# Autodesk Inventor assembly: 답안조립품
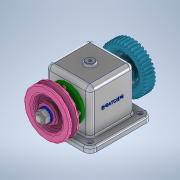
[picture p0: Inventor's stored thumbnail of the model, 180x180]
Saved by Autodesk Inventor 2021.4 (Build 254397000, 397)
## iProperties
Created: 2022-07
Part Number: 답안조립품
Document SubType Name: Assembly
Designer: j
Author: j
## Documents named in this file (12)
- C:\Users\j\Desktop\720706V1003\답안조립품.iam
- C:\Users\j\Desktop\720706V1003\본체.ipt
- C:\Users\j\Desktop\720706V1003\V벨트풀리.ipt
- C:\Users\j\Desktop\720706V1003\너트 M12x1.25.ipt
- C:\Users\j\Desktop\720706V1003\베어링 6204.ipt
- C:\Users\j\Desktop\720706V1003\볼트 M4x0.7.ipt
- C:\Users\j\Desktop\720706V1003\스퍼기어.ipt
- C:\Users\j\Desktop\720706V1003\오일실 20x35x8.ipt
- C:\Users\j\Desktop\720706V1003\와셔 12x24.ipt
- C:\Users\j\Desktop\720706V1003\축.ipt
- C:\Users\j\Desktop\720706V1003\커버.ipt
- C:\Users\j\Desktop\720706V1003\키 5x5.ipt
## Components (1 placed, 1 different names)
1. V벨트풀리:1
## Named parameters: d4_d1 = 0, d5_d2 = 0, d6_d3 = 0, d7_d0 = 0, d16_d14 = 0, d17_d15 = 0
